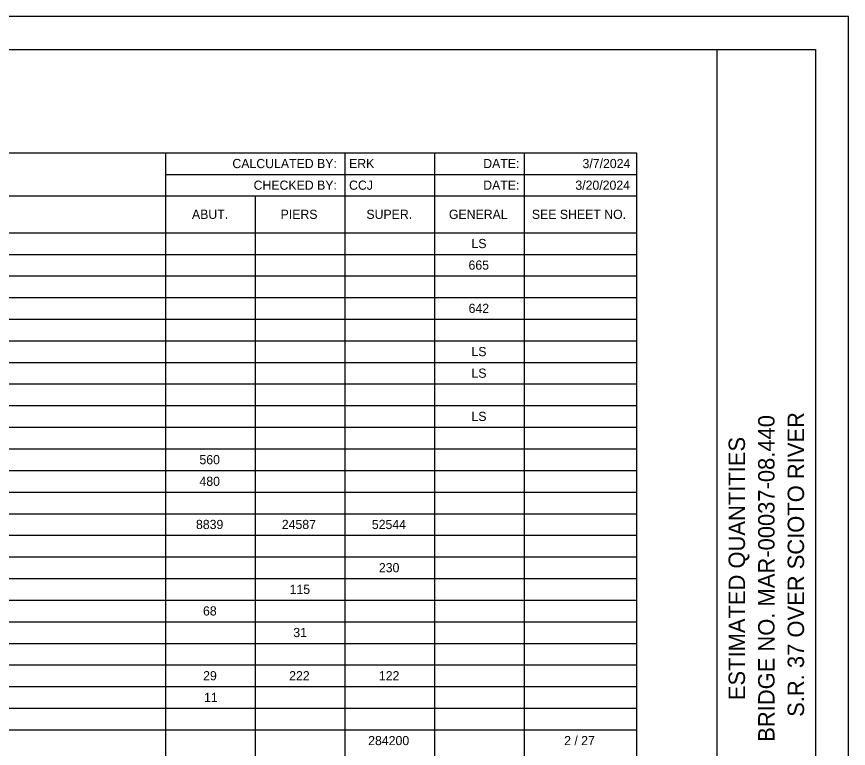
# Model space of a CAD drawing. Extents: x 0 to 34, y 0 to 22.
# Drawn here: x 21.33 to 34, y 10.85 to 22 of the extents above; entities that cross this region are included whole.
import ezdxf

# ---------------------------------------------------------------- set-up
doc = ezdxf.new("R2010")
doc.units = 0
for name, color, linetype in [('Default', 7, 'Continuous'), ('SH_Border', 7, 'Continuous'), ('SH_Cut_Line', 7, 'Continuous'), ('SH_Data', 7, 'Continuous')]:
    doc.layers.add(name, color=color, linetype=linetype)

msp = doc.modelspace()

# ---------------------------------------------------------------- linework, layer by layer
at = {"layer": 'Default'}
for p, q in [((2.395, 19.926), (30.774, 19.926)), ((23.592, 19.926), (23.592, 2.236)), ((26.326, 19.926), (26.326, 2.236)), ((27.694, 19.926), (27.694, 2.236)), ((29.061, 19.926), (29.061, 2.236)), ((30.774, 19.926), (30.774, 2.236)), ((23.592, 19.596), (30.774, 19.596)), ((2.395, 19.267), (30.774, 19.267)), ((24.959, 19.267), (24.959, 2.236)), ((2.395, 18.707), (30.774, 18.707)), ((2.395, 18.377), (30.774, 18.377)), ((2.395, 18.048), (30.774, 18.048)), ((2.395, 17.718), (30.774, 17.718)), ((2.395, 17.389), (30.774, 17.389)), ((2.395, 17.06), (30.774, 17.06)), ((2.395, 16.73), (30.774, 16.73)), ((2.395, 16.401), (30.774, 16.401)), ((2.395, 16.071), (30.774, 16.071)), ((2.395, 15.742), (30.774, 15.742)), ((2.395, 15.413), (30.774, 15.413)), ((2.395, 15.083), (30.774, 15.083)), ((2.395, 14.754), (30.774, 14.754)), ((2.395, 14.424), (30.774, 14.424)), ((2.395, 14.095), (30.774, 14.095)), ((2.395, 13.766), (30.774, 13.766)), ((2.395, 13.436), (30.774, 13.436)), ((2.395, 13.107), (30.774, 13.107)), ((2.395, 12.777), (30.774, 12.777)), ((2.395, 12.448), (30.774, 12.448)), ((2.395, 12.118), (30.774, 12.118)), ((2.395, 11.789), (30.774, 11.789)), ((2.395, 11.46), (30.774, 11.46)), ((2.395, 11.13), (30.774, 11.13))]:
    msp.add_line(p, q, dxfattribs=at)
at = {"layer": 'SH_Border'}
msp.add_line((32, 0.5), (32, 21.5), dxfattribs=at)
msp.add_lwpolyline([(1.5, 21.5), (33.5, 21.5), (33.5, 0.5), (1.5, 0.5)], close=True, dxfattribs=at)
at = {"layer": 'SH_Cut_Line'}
msp.add_lwpolyline([(0, 0), (34, 0), (34, 22), (0, 22)], close=True, dxfattribs=at)

# ---------------------------------------------------------------- texts
at = {"layer": 'Default'}
for s, p in [('CALCULATED BY:', (24.614, 19.691)), ('ERK', (26.392, 19.691)), ('DATE:', (28.436, 19.691)), ('3/7/2024', (29.949, 19.691)), ('CHECKED BY:', (24.937, 19.361)), ('CCJ', (26.392, 19.361)), ('DATE:', (28.436, 19.361)), ('3/20/2024', (29.84, 19.361)), ('ABUT.', (23.998, 18.917)), ('PIERS', (25.349, 18.917)), ('SUPER.', (26.656, 18.917)), ('GENERAL', (27.913, 18.917)), ('SEE SHEET NO.', (29.177, 18.917)), ('LS', (28.257, 18.472)), ('665', (28.212, 18.143)), ('642', (28.213, 17.484)), ('LS', (28.257, 16.825)), ('LS', (28.257, 16.496)), ('LS', (28.257, 15.837)), ('560', (24.112, 15.178)), ('480', (24.112, 14.848)), ('8839', (24.059, 14.19)), ('24587', (25.367, 14.19)), ('52544', (26.739, 14.19)), ('230', (26.846, 13.531)), ('115', (25.486, 13.201)), ('68', (24.166, 12.872)), ('31', (25.542, 12.543)), ('29', (24.168, 11.884)), ('222', (25.479, 11.884)), ('122', (26.846, 11.884)), ('11', (24.182, 11.554)), ('284200', (26.683, 10.896)), ('2 / 27', (29.669, 10.896))]:
    msp.add_text(s, height=0.14, dxfattribs=at).set_placement(p)
at = {"layer": 'SH_Data'}
for s, p in [('BRIDGE NO. MAR-00037-08.440', (32.875, 10.948)), ('S.R. 37 OVER SCIOTO RIVER', (33.325, 11.328)), ('ESTIMATED QUANTITIES', (32.425, 11.582))]:
    msp.add_text(s, height=0.25, rotation=90, dxfattribs=at).set_placement(p)

doc.saveas('drawing.dxf')
